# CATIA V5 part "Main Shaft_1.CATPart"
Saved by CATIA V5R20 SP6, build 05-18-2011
Part number: Main Shaft
Bounding box of the stored display mesh (mm): x -54.997 to 54.997, y -109 to 35, z 102.002 to 211.998
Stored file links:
  E:\#01 CATIA Lecture Materials\#06 DMU\#04 DMU Page01 KIN EX04\Main Shaft_1.CATPart
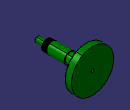
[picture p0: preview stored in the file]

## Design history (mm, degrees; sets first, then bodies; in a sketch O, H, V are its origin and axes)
Body1 (main body)
Body2
  Solid1: solid without history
